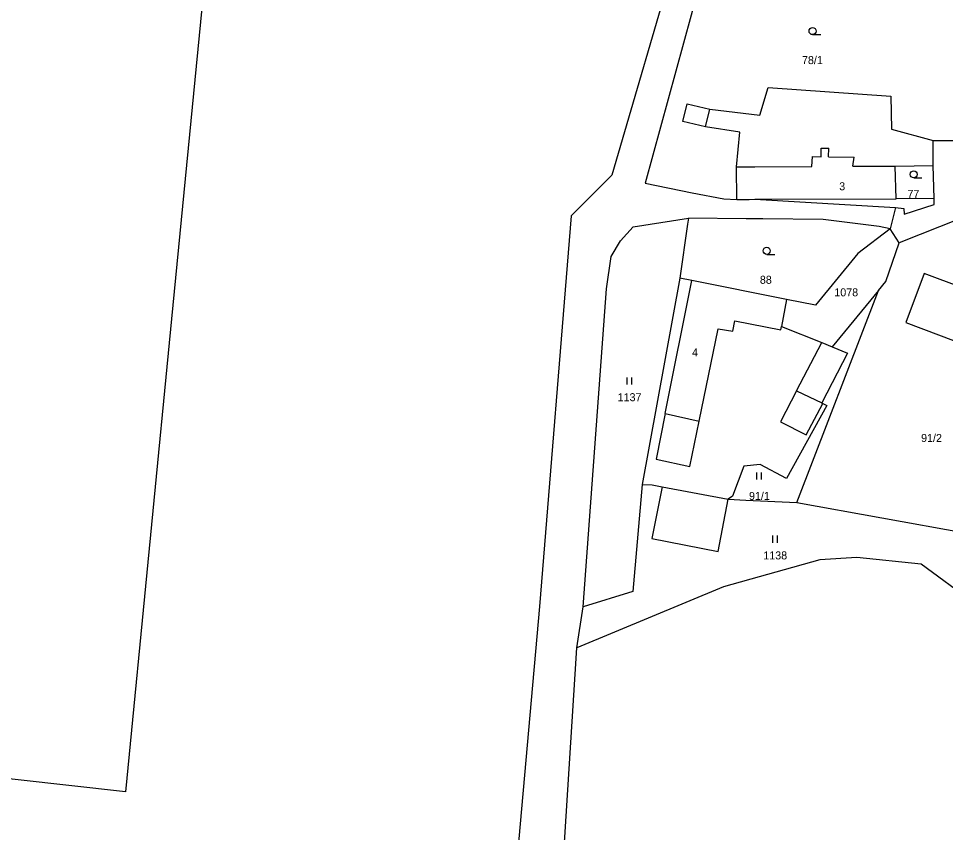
# Model space of a CAD drawing. Extents: x -746176 to -739709, y -1128407 to -1124482.
# Drawn here: x -742573.8 to -742377, y -1126240.2 to -1126067.4 of the extents above; entities that cross this region are included whole.
import ezdxf

# ---------------------------------------------------------------- set-up
doc = ezdxf.new("R2010")
doc.units = 0
for name, color, linetype in [('Hranice parcel', 7, 'Continuous'), ('Parcelní čísla', 7, 'Continuous'), ('Vnitřní kresba', 7, 'Continuous'), ('Značky kultur', 7, 'Continuous')]:
    doc.layers.add(name, color=color, linetype=linetype)

msp = doc.modelspace()

# ---------------------------------------------------------------- linework, layer by layer
at = {"layer": 'Hranice parcel'}
for p, q in [((-742379.56, -1126098.64), (-742379.6, -1126093.36)), ((-742379.39, -1126105.64), (-742379.56, -1126098.64)), ((-742387.54, -1126107.59), (-742388.7, -1126112.08)), ((-742386.77, -1126115.04), (-742388.7, -1126112.08)), ((-742389.6, -1126123.26), (-742386.77, -1126115.04)), ((-742433.38, -1126122.54), (-742441.38, -1126166.33)), ((-742391.19, -1126125.19), (-742389.6, -1126123.26)), ((-742408.55, -1126170.19), (-742391.19, -1126125.19)), ((-742391.19, -1126125.19), (-742401.05, -1126137.14)), ((-742408.55, -1126170.19), (-742366.28, -1126177.8)), ((-742455.22, -1126201.03), (-742453.88, -1126192.33))]:
    msp.add_line(p, q, dxfattribs=at)
for points in [[(-742530.79, -1126023.12), (-742541.03, -1126128.32), (-742551.09, -1126231.6), (-742645.51, -1126221.02)], [(-742433.87, -1126052.94), (-742447.8, -1126100.68), (-742456.41, -1126109.29), (-742463.16, -1126192.21), (-742472.54, -1126297.27), (-742476.24, -1126360.79), (-742482.39, -1126414.71)], [(-742427.68, -1126054.77), (-742440.74, -1126102.42), (-742430.76, -1126104.41), (-742424.03, -1126105.75), (-742421.29, -1126105.88)], [(-742421.29, -1126105.88), (-742421.35, -1126098.94), (-742420.61, -1126091.6), (-742427.91, -1126090.46), (-742432.7, -1126089.32), (-742431.8, -1126085.57), (-742427.02, -1126086.71), (-742416.37, -1126087.94), (-742414.61, -1126082.07), (-742388.6, -1126083.94), (-742388.43, -1126090.91), (-742379.6, -1126093.36)], [(-742379.6, -1126093.36), (-742370.19, -1126093.35), (-742362.62, -1126088.05), (-742361.35, -1126086.4)], [(-742379.39, -1126105.64), (-742387.46, -1126105.73), (-742387.67, -1126098.78), (-742379.56, -1126098.64)], [(-742421.29, -1126105.88), (-742418.62, -1126105.84), (-742417.46, -1126105.82), (-742387.54, -1126107.59)], [(-742387.54, -1126107.59), (-742385.77, -1126107.77), (-742385.76, -1126108.96), (-742379.36, -1126106.92), (-742379.39, -1126105.64)], [(-742453.88, -1126192.33), (-742448.94, -1126124.82), (-742447.92, -1126117.98), (-742446, -1126114.6), (-742443.31, -1126111.65), (-742431.56, -1126109.81)], [(-742431.56, -1126109.81), (-742431.74, -1126111.07), (-742433.38, -1126122.54)], [(-742388.7, -1126112.08), (-742391.06, -1126111.59), (-742402.96, -1126110.08), (-742415.74, -1126109.96), (-742419.27, -1126109.93), (-742431.56, -1126109.81)], [(-742351.14, -1126116.55), (-742365.05, -1126112.26), (-742373.77, -1126109.92), (-742386.77, -1126115.04)], [(-742388.7, -1126112.08), (-742395.57, -1126117.34), (-742404.55, -1126128.31), (-742410.69, -1126127.09)], [(-742410.69, -1126127.09), (-742430.85, -1126123.08), (-742433.38, -1126122.54)], [(-742360.61, -1126129.44), (-742370.56, -1126125.67), (-742369.93, -1126124), (-742372.74, -1126122.95), (-742373.37, -1126124.6), (-742381.46, -1126121.54), (-742385.41, -1126131.94), (-742364.54, -1126139.8), (-742360.61, -1126129.44)], [(-742410.69, -1126127.09), (-742411.76, -1126132.8), (-742403.21, -1126136.23), (-742401.05, -1126137.14)], [(-742401.05, -1126137.14), (-742397.77, -1126138.5), (-742403.21, -1126149.03), (-742402.98, -1126149.15), (-742402.18, -1126149.59), (-742410.69, -1126165.08), (-742416.29, -1126162.13), (-742419.8, -1126162.46), (-742422.21, -1126168.79), (-742423.12, -1126169.49)], [(-742441.38, -1126166.33), (-742443.37, -1126189.04), (-742453.88, -1126192.33)], [(-742441.38, -1126166.33), (-742439.21, -1126166.45), (-742437.12, -1126166.85), (-742439.28, -1126177.82), (-742425.2, -1126180.54), (-742423.12, -1126169.49)], [(-742423.12, -1126169.49), (-742419.32, -1126169.67), (-742408.55, -1126170.19)], [(-742371.13, -1126191.3), (-742382.1, -1126183.23), (-742395.78, -1126181.85), (-742403.65, -1126182.31), (-742424.12, -1126188.09), (-742455.22, -1126201.03)], [(-742521.95, -1126773.52), (-742504.56, -1126672.68), (-742497, -1126628.23), (-742488.98, -1126567.9), (-742478.35, -1126466.13), (-742467.6, -1126363.23), (-742463.32, -1126296.13), (-742459.73, -1126263.65), (-742452.82, -1126263.88), (-742450.23, -1126260.63), (-742452.38, -1126257.65), (-742458.75, -1126256.81), (-742455.22, -1126201.03)]]:
    msp.add_lwpolyline(points, dxfattribs=at)
at = {"layer": 'Vnitřní kresba'}
for p, q in [((-742427.91, -1126090.46), (-742427.02, -1126086.71)), ((-742403.39, -1126096.78), (-742403.37, -1126094.93)), ((-742403.37, -1126094.93), (-742401.75, -1126094.95)), ((-742401.77, -1126096.8), (-742401.75, -1126094.95)), ((-742405.37, -1126098.85), (-742405.22, -1126096.76)), ((-742405.22, -1126096.76), (-742403.39, -1126096.78)), ((-742401.77, -1126096.8), (-742396.32, -1126096.85)), ((-742396.62, -1126098.81), (-742396.32, -1126096.85)), ((-742421.35, -1126098.94), (-742417.44, -1126098.9)), ((-742417.44, -1126098.9), (-742405.37, -1126098.85)), ((-742396.62, -1126098.81), (-742387.67, -1126098.78)), ((-742417.46, -1126105.82), (-742387.46, -1126105.73)), ((-742436.45, -1126151.3), (-742430.85, -1126123.08)), ((-742422.1, -1126133.81), (-742421.67, -1126131.64)), ((-742421.67, -1126131.64), (-742411.89, -1126133.49)), ((-742411.89, -1126133.49), (-742411.76, -1126132.8)), ((-742429.26, -1126152.92), (-742425.23, -1126133.31)), ((-742425.23, -1126133.31), (-742422.1, -1126133.81)), ((-742408.58, -1126146.46), (-742403.21, -1126136.23)), ((-742408.58, -1126146.46), (-742411.97, -1126153.04)), ((-742408.58, -1126146.46), (-742403.21, -1126149.03)), ((-742406.52, -1126155.83), (-742402.98, -1126149.15)), ((-742436.45, -1126151.3), (-742438.39, -1126161)), ((-742436.45, -1126151.3), (-742429.26, -1126152.92)), ((-742431.21, -1126162.5), (-742429.26, -1126152.92)), ((-742411.97, -1126153.04), (-742406.52, -1126155.83)), ((-742438.39, -1126161), (-742431.21, -1126162.5)), ((-742437.12, -1126166.85), (-742423.12, -1126169.49))]:
    msp.add_line(p, q, dxfattribs=at)
at = {"layer": 'Značky kultur'}
for p, q in [((-742405.18, -1126070.87), (-742403.43, -1126070.87)), ((-742383.7, -1126101.27), (-742381.95, -1126101.27)), ((-742414.92, -1126117.5), (-742413.17, -1126117.5)), ((-742444.57, -1126145.12), (-742444.57, -1126143.62)), ((-742443.57, -1126145.12), (-742443.57, -1126143.62)), ((-742417.04, -1126165.29), (-742417.04, -1126163.79)), ((-742416.04, -1126165.29), (-742416.04, -1126163.79)), ((-742413.64, -1126178.7), (-742413.64, -1126177.2)), ((-742412.64, -1126178.7), (-742412.64, -1126177.2))]:
    msp.add_line(p, q, dxfattribs=at)
for centre in [(-742405.18, -1126070.12), (-742383.7, -1126100.52), (-742414.92, -1126116.75)]:
    msp.add_circle(centre, 0.75, dxfattribs=at)

# ---------------------------------------------------------------- texts
at = {"layer": 'Parcelní čísla'}
for s, p in [('78/1', (-742407.43, -1126077.12)), ('3', (-742399.53, -1126103.9)), ('77', (-742385.04, -1126105.53)), ('88', (-742416.37, -1126123.75)), ('1078', (-742400.56, -1126126.41)), ('4', (-742430.78, -1126139.17)), ('1137', (-742446.57, -1126148.67)), ('91/2', (-742382.14, -1126157.33)), ('91/1', (-742418.68, -1126169.63)), ('1138', (-742415.64, -1126182.25))]:
    msp.add_text(s, height=1.7, dxfattribs=at).set_placement(p)

doc.saveas('drawing.dxf')
